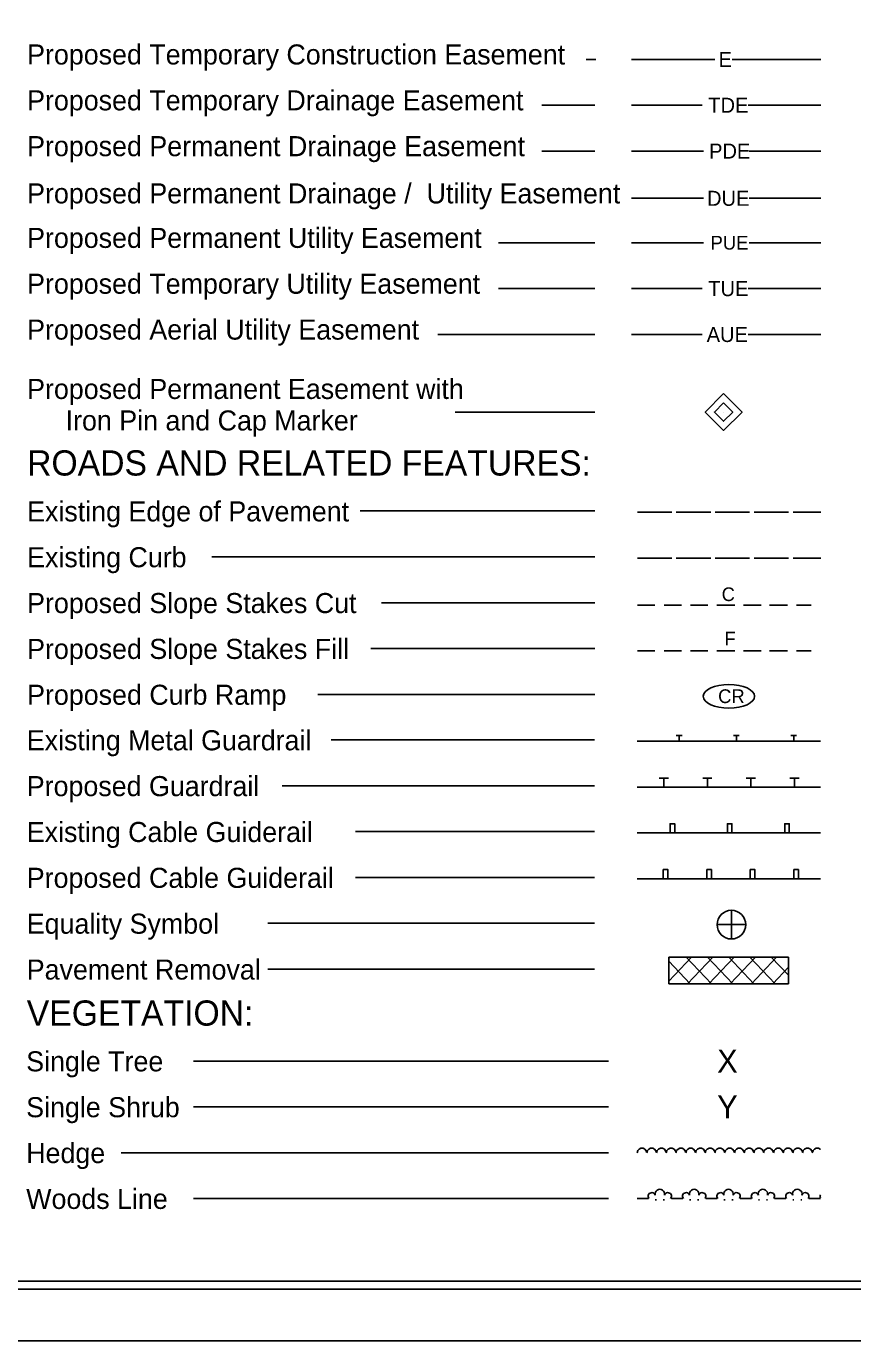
# Model space of a CAD drawing. Extents: x 573851.1 to 573884.7, y -53293.5 to -53271.5.
# Drawn here: x 573862.29 to 573869.5, y -53293.51 to -53282.04 of the extents above; entities that cross this region are included whole.
import ezdxf

# ---------------------------------------------------------------- set-up
doc = ezdxf.new("R2010")
doc.units = 0
for name, color, linetype in [('Prop Easement Permanent Drainage Utility', 7, 'Continuous'), ('Prop ROW Permanent Easement CELL', 7, 'Continuous'), ('Prop WCC CELL', 7, 'Continuous'), ('Sheet Cutting Line CELL', 7, 'Continuous'), ('Sheet Plot Border Inside CELL', 7, 'Continuous'), ('Sheet Plot Border Outside CELL', 7, 'Continuous'), ('Sheet Symbology CELL', 7, 'Continuous')]:
    doc.layers.add(name, color=color, linetype=linetype)

msp = doc.modelspace()

# ---------------------------------------------------------------- linework, layer by layer
at = {"layer": 'Prop Easement Permanent Drainage Utility'}
for p, q in [((573867.575, -53283.543), (573868.201, -53283.543)), ((573867.575, -53283.543), (573868.201, -53283.543)), ((573868.601, -53283.543), (573869.225, -53283.543)), ((573868.601, -53283.543), (573869.225, -53283.543))]:
    msp.add_line(p, q, dxfattribs=at)
at = {"layer": 'Prop ROW Permanent Easement CELL'}
msp.add_line((573868.378, -53285.408), (573868.378, -53285.408), dxfattribs=at)
for points in [[(573868.378, -53285.247), (573868.539, -53285.408), (573868.378, -53285.569), (573868.217, -53285.408)], [(573868.378, -53285.327), (573868.458, -53285.408), (573868.378, -53285.488), (573868.297, -53285.408)]]:
    msp.add_lwpolyline(points, close=True, dxfattribs=at)
at = {"layer": 'Prop WCC CELL'}
msp.add_ellipse((573868.424, -53287.888), major_axis=(0.224, 0), ratio=0.462467, dxfattribs=at)
at = {"layer": 'Sheet Cutting Line CELL'}
msp.add_line((573851.065, -53293.51), (573884.745, -53293.51), dxfattribs=at)
at = {"layer": 'Sheet Plot Border Inside CELL'}
msp.add_lwpolyline([(573851.325, -53293.061), (573884.655, -53293.061), (573884.655, -53271.959), (573851.325, -53271.959)], close=True, dxfattribs=at)
at = {"layer": 'Sheet Plot Border Outside CELL'}
msp.add_lwpolyline([(573851.065, -53293.51), (573884.745, -53293.51), (573884.745, -53271.51), (573851.065, -53271.51)], close=True, dxfattribs=at)
at = {"layer": 'Sheet Symbology CELL'}
for p, q in [((573867.262, -53282.331), (573867.179, -53282.331)), ((573867.575, -53282.331), (573867.627, -53282.331)), ((573867.627, -53282.331), (573868.302, -53282.331)), ((573868.452, -53282.331), (573869.127, -53282.331)), ((573869.127, -53282.331), (573869.225, -53282.331)), ((573867.254, -53282.731), (573866.791, -53282.731)), ((573867.575, -53282.731), (573867.642, -53282.731)), ((573867.642, -53282.731), (573868.192, -53282.731)), ((573868.592, -53282.731), (573869.142, -53282.731)), ((573869.142, -53282.731), (573869.225, -53282.731)), ((573867.254, -53283.131), (573866.791, -53283.131)), ((573867.575, -53283.131), (573867.651, -53283.131)), ((573867.651, -53283.131), (573868.201, -53283.131)), ((573868.601, -53283.131), (573869.151, -53283.131)), ((573869.151, -53283.131), (573869.225, -53283.131)), ((573867.254, -53283.931), (573866.412, -53283.931)), ((573867.575, -53283.931), (573867.652, -53283.931)), ((573867.652, -53283.931), (573868.202, -53283.931)), ((573868.602, -53283.931), (573869.152, -53283.931)), ((573869.152, -53283.931), (573869.225, -53283.931)), ((573867.254, -53284.331), (573866.412, -53284.331)), ((573867.575, -53284.331), (573867.642, -53284.331)), ((573867.642, -53284.331), (573868.192, -53284.331)), ((573868.592, -53284.331), (573869.142, -53284.331)), ((573869.142, -53284.331), (573869.225, -53284.331)), ((573867.254, -53284.731), (573865.885, -53284.731)), ((573867.575, -53284.731), (573867.642, -53284.731)), ((573867.642, -53284.731), (573868.192, -53284.731)), ((573868.592, -53284.731), (573869.142, -53284.731)), ((573869.142, -53284.731), (573869.225, -53284.731)), ((573867.254, -53285.408), (573866.034, -53285.408)), ((573867.254, -53286.271), (573865.207, -53286.271)), ((573867.625, -53286.282), (573867.925, -53286.282)), ((573867.965, -53286.282), (573868.265, -53286.282)), ((573868.305, -53286.282), (573868.605, -53286.282)), ((573868.645, -53286.282), (573868.945, -53286.282)), ((573868.985, -53286.282), (573869.225, -53286.282)), ((573867.254, -53286.671), (573863.911, -53286.671)), ((573867.625, -53286.682), (573867.925, -53286.682)), ((573867.965, -53286.682), (573868.265, -53286.682)), ((573868.305, -53286.682), (573868.605, -53286.682)), ((573868.645, -53286.682), (573868.945, -53286.682)), ((573868.985, -53286.682), (573869.225, -53286.682)), ((573867.254, -53287.071), (573865.391, -53287.071)), ((573867.625, -53287.092), (573867.777, -53287.092)), ((573868.011, -53287.092), (573867.86, -53287.092)), ((573868.241, -53287.092), (573868.089, -53287.092)), ((573868.476, -53287.092), (573868.32, -53287.092)), ((573868.705, -53287.092), (573868.55, -53287.092)), ((573868.936, -53287.092), (573868.779, -53287.092)), ((573869.142, -53287.092), (573869.014, -53287.092)), ((573867.254, -53287.471), (573865.3, -53287.471)), ((573867.625, -53287.492), (573867.777, -53287.492)), ((573868.011, -53287.492), (573867.86, -53287.492)), ((573868.241, -53287.492), (573868.089, -53287.492)), ((573868.476, -53287.492), (573868.32, -53287.492)), ((573868.705, -53287.492), (573868.55, -53287.492)), ((573868.936, -53287.492), (573868.779, -53287.492)), ((573869.142, -53287.492), (573869.014, -53287.492)), ((573867.254, -53287.871), (573864.836, -53287.871)), ((573867.965, -53288.23), (573868.015, -53288.23)), ((573867.99, -53288.28), (573867.99, -53288.23)), ((573868.465, -53288.23), (573868.515, -53288.23)), ((573868.49, -53288.28), (573868.49, -53288.23)), ((573868.965, -53288.23), (573869.015, -53288.23)), ((573868.99, -53288.28), (573868.99, -53288.23)), ((573867.251, -53288.268), (573864.954, -53288.268)), ((573867.622, -53288.28), (573869.222, -53288.28)), ((573867.251, -53288.668), (573864.526, -53288.668)), ((573869.222, -53288.68), (573867.622, -53288.68)), ((573867.816, -53288.601), (573867.896, -53288.601)), ((573867.856, -53288.68), (573867.856, -53288.601)), ((573868.196, -53288.601), (573868.276, -53288.601)), ((573868.236, -53288.68), (573868.236, -53288.601)), ((573868.576, -53288.601), (573868.656, -53288.601)), ((573868.616, -53288.68), (573868.616, -53288.601)), ((573868.956, -53288.601), (573869.036, -53288.601)), ((573868.996, -53288.68), (573868.996, -53288.601)), ((573867.251, -53289.068), (573865.165, -53289.068)), ((573867.622, -53289.08), (573869.222, -53289.08)), ((573867.251, -53289.468), (573865.165, -53289.468)), ((573867.622, -53289.48), (573869.222, -53289.48)), ((573868.446, -53289.755), (573868.446, -53289.88)), ((573867.251, -53289.868), (573864.399, -53289.868)), ((573868.321, -53289.88), (573868.446, -53289.88)), ((573868.446, -53289.88), (573868.446, -53290.005)), ((573868.446, -53289.88), (573868.571, -53289.88)), ((573867.901, -53290.163), (573868.943, -53290.163)), ((573867.901, -53290.397), (573867.901, -53290.163)), ((573867.901, -53290.175), (573867.912, -53290.163)), ((573867.901, -53290.374), (573868.098, -53290.163)), ((573868.272, -53290.397), (573868.052, -53290.163)), ((573868.064, -53290.397), (573868.284, -53290.163)), ((573868.457, -53290.397), (573868.238, -53290.163)), ((573868.249, -53290.397), (573868.47, -53290.163)), ((573868.643, -53290.397), (573868.423, -53290.163)), ((573868.435, -53290.397), (573868.655, -53290.163)), ((573868.829, -53290.397), (573868.608, -53290.163)), ((573868.621, -53290.397), (573868.84, -53290.163)), ((573868.943, -53290.322), (573868.794, -53290.163)), ((573868.943, -53290.163), (573868.943, -53290.397)), ((573867.251, -53290.268), (573864.399, -53290.268)), ((573868.086, -53290.397), (573867.901, -53290.199)), ((573868.806, -53290.397), (573868.943, -53290.251)), ((573868.943, -53290.397), (573867.901, -53290.397)), ((573867.374, -53291.07), (573863.751, -53291.07)), ((573867.374, -53291.47), (573863.751, -53291.47)), ((573867.374, -53291.87), (573863.12, -53291.87)), ((573867.622, -53291.87), (573867.628, -53291.851)), ((573867.628, -53291.851), (573867.64, -53291.838)), ((573867.64, -53291.838), (573867.656, -53291.829)), ((573867.656, -53291.829), (573867.675, -53291.829)), ((573867.675, -53291.829), (573867.691, -53291.839)), ((573867.691, -53291.839), (573867.702, -53291.852)), ((573867.702, -53291.852), (573867.706, -53291.869)), ((573867.707, -53291.87), (573867.713, -53291.851)), ((573867.713, -53291.851), (573867.725, -53291.838)), ((573867.725, -53291.838), (573867.741, -53291.829)), ((573867.741, -53291.829), (573867.76, -53291.829)), ((573867.76, -53291.829), (573867.776, -53291.839)), ((573867.776, -53291.839), (573867.787, -53291.852)), ((573867.787, -53291.852), (573867.791, -53291.869)), ((573867.792, -53291.87), (573867.798, -53291.851)), ((573867.798, -53291.851), (573867.81, -53291.838)), ((573867.81, -53291.838), (573867.826, -53291.829)), ((573867.826, -53291.829), (573867.845, -53291.829)), ((573867.845, -53291.829), (573867.861, -53291.839)), ((573867.861, -53291.839), (573867.872, -53291.852)), ((573867.872, -53291.852), (573867.876, -53291.869)), ((573867.877, -53291.87), (573867.883, -53291.851)), ((573867.883, -53291.851), (573867.895, -53291.838)), ((573867.895, -53291.838), (573867.911, -53291.829)), ((573867.911, -53291.829), (573867.93, -53291.829)), ((573867.93, -53291.829), (573867.946, -53291.839)), ((573867.946, -53291.839), (573867.957, -53291.852)), ((573867.957, -53291.852), (573867.961, -53291.869)), ((573867.962, -53291.87), (573867.968, -53291.851)), ((573867.968, -53291.851), (573867.98, -53291.838)), ((573867.98, -53291.838), (573867.996, -53291.829)), ((573867.996, -53291.829), (573868.015, -53291.829)), ((573868.015, -53291.829), (573868.031, -53291.839)), ((573868.031, -53291.839), (573868.042, -53291.852)), ((573868.042, -53291.852), (573868.046, -53291.869)), ((573868.047, -53291.87), (573868.053, -53291.851)), ((573868.053, -53291.851), (573868.065, -53291.838)), ((573868.065, -53291.838), (573868.081, -53291.829)), ((573868.081, -53291.829), (573868.1, -53291.829)), ((573868.1, -53291.829), (573868.116, -53291.839)), ((573868.116, -53291.839), (573868.127, -53291.852)), ((573868.127, -53291.852), (573868.131, -53291.869)), ((573868.132, -53291.87), (573868.138, -53291.851)), ((573868.138, -53291.851), (573868.15, -53291.838)), ((573868.15, -53291.838), (573868.166, -53291.829)), ((573868.166, -53291.829), (573868.185, -53291.829)), ((573868.185, -53291.829), (573868.201, -53291.839)), ((573868.201, -53291.839), (573868.212, -53291.852)), ((573868.212, -53291.852), (573868.216, -53291.869)), ((573868.217, -53291.87), (573868.223, -53291.851)), ((573868.223, -53291.851), (573868.235, -53291.838)), ((573868.235, -53291.838), (573868.251, -53291.829)), ((573868.251, -53291.829), (573868.27, -53291.829)), ((573868.27, -53291.829), (573868.286, -53291.839)), ((573868.286, -53291.839), (573868.297, -53291.852)), ((573868.297, -53291.852), (573868.301, -53291.869)), ((573868.302, -53291.87), (573868.308, -53291.851)), ((573868.308, -53291.851), (573868.32, -53291.838)), ((573868.32, -53291.838), (573868.336, -53291.829)), ((573868.336, -53291.829), (573868.355, -53291.829)), ((573868.355, -53291.829), (573868.371, -53291.839)), ((573868.371, -53291.839), (573868.382, -53291.852)), ((573868.382, -53291.852), (573868.386, -53291.869)), ((573868.387, -53291.87), (573868.393, -53291.851)), ((573868.393, -53291.851), (573868.405, -53291.838)), ((573868.405, -53291.838), (573868.421, -53291.829)), ((573868.421, -53291.829), (573868.44, -53291.829)), ((573868.44, -53291.829), (573868.456, -53291.839)), ((573868.456, -53291.839), (573868.467, -53291.852)), ((573868.467, -53291.852), (573868.471, -53291.869)), ((573868.472, -53291.87), (573868.478, -53291.851)), ((573868.478, -53291.851), (573868.49, -53291.838)), ((573868.49, -53291.838), (573868.506, -53291.829)), ((573868.506, -53291.829), (573868.525, -53291.829)), ((573868.525, -53291.829), (573868.541, -53291.839)), ((573868.541, -53291.839), (573868.552, -53291.852)), ((573868.552, -53291.852), (573868.556, -53291.869)), ((573868.557, -53291.87), (573868.563, -53291.851)), ((573868.563, -53291.851), (573868.575, -53291.838)), ((573868.575, -53291.838), (573868.591, -53291.829)), ((573868.591, -53291.829), (573868.61, -53291.829)), ((573868.61, -53291.829), (573868.626, -53291.839)), ((573868.626, -53291.839), (573868.637, -53291.852)), ((573868.637, -53291.852), (573868.641, -53291.869)), ((573868.642, -53291.87), (573868.648, -53291.851)), ((573868.648, -53291.851), (573868.66, -53291.838)), ((573868.66, -53291.838), (573868.676, -53291.829)), ((573868.676, -53291.829), (573868.695, -53291.829)), ((573868.695, -53291.829), (573868.711, -53291.839)), ((573868.711, -53291.839), (573868.722, -53291.852)), ((573868.722, -53291.852), (573868.726, -53291.869)), ((573868.727, -53291.87), (573868.733, -53291.851)), ((573868.733, -53291.851), (573868.745, -53291.838)), ((573868.745, -53291.838), (573868.761, -53291.829)), ((573868.761, -53291.829), (573868.78, -53291.829)), ((573868.78, -53291.829), (573868.796, -53291.839)), ((573868.796, -53291.839), (573868.807, -53291.852)), ((573868.807, -53291.852), (573868.811, -53291.869)), ((573868.812, -53291.87), (573868.818, -53291.851)), ((573868.818, -53291.851), (573868.83, -53291.838)), ((573868.83, -53291.838), (573868.846, -53291.829)), ((573868.846, -53291.829), (573868.865, -53291.829)), ((573868.865, -53291.829), (573868.881, -53291.839)), ((573868.881, -53291.839), (573868.892, -53291.852)), ((573868.892, -53291.852), (573868.896, -53291.869)), ((573868.897, -53291.87), (573868.903, -53291.851)), ((573868.903, -53291.851), (573868.915, -53291.838)), ((573868.915, -53291.838), (573868.931, -53291.829)), ((573868.931, -53291.829), (573868.95, -53291.829)), ((573868.95, -53291.829), (573868.966, -53291.839)), ((573868.966, -53291.839), (573868.977, -53291.852)), ((573868.977, -53291.852), (573868.981, -53291.869)), ((573868.982, -53291.87), (573868.988, -53291.851)), ((573868.988, -53291.851), (573869, -53291.838)), ((573869, -53291.838), (573869.016, -53291.829)), ((573869.016, -53291.829), (573869.035, -53291.829)), ((573869.035, -53291.829), (573869.051, -53291.839)), ((573869.051, -53291.839), (573869.062, -53291.852)), ((573869.062, -53291.852), (573869.066, -53291.869)), ((573869.067, -53291.87), (573869.073, -53291.851)), ((573869.073, -53291.851), (573869.085, -53291.838)), ((573869.085, -53291.838), (573869.101, -53291.829)), ((573869.101, -53291.829), (573869.12, -53291.829)), ((573869.12, -53291.829), (573869.136, -53291.839)), ((573869.136, -53291.839), (573869.147, -53291.852)), ((573869.147, -53291.852), (573869.151, -53291.869)), ((573869.152, -53291.87), (573869.158, -53291.851)), ((573869.158, -53291.851), (573869.17, -53291.838)), ((573869.17, -53291.838), (573869.186, -53291.829)), ((573869.186, -53291.829), (573869.205, -53291.829)), ((573869.205, -53291.829), (573869.221, -53291.839)), ((573869.221, -53291.839), (573869.222, -53291.84)), ((573867.374, -53292.27), (573863.751, -53292.27)), ((573867.622, -53292.27), (573867.722, -53292.27)), ((573867.781, -53292.28), (573867.791, -53292.28)), ((573867.851, -53292.28), (573867.861, -53292.28)), ((573867.922, -53292.27), (573868.022, -53292.27)), ((573868.081, -53292.28), (573868.091, -53292.28)), ((573868.151, -53292.28), (573868.161, -53292.28)), ((573868.222, -53292.27), (573868.322, -53292.27)), ((573868.381, -53292.28), (573868.391, -53292.28)), ((573868.451, -53292.28), (573868.461, -53292.28)), ((573868.522, -53292.27), (573868.622, -53292.27)), ((573868.681, -53292.28), (573868.691, -53292.28)), ((573868.751, -53292.28), (573868.761, -53292.28)), ((573868.822, -53292.27), (573868.922, -53292.27)), ((573868.981, -53292.28), (573868.991, -53292.28)), ((573869.051, -53292.28), (573869.061, -53292.28)), ((573869.122, -53292.27), (573869.222, -53292.27))]:
    msp.add_line(p, q, dxfattribs=at)
for points in [[(573884.405, -53272.01), (573854.405, -53272.01), (573854.405, -53292.989), (573884.405, -53292.989)], [(573867.911, -53289.08), (573867.951, -53289.08), (573867.951, -53289), (573867.911, -53289)], [(573868.411, -53289.08), (573868.451, -53289.08), (573868.451, -53289), (573868.411, -53289)], [(573868.911, -53289.08), (573868.951, -53289.08), (573868.951, -53289), (573868.911, -53289)], [(573867.851, -53289.4), (573867.891, -53289.4), (573867.891, -53289.48), (573867.851, -53289.48)], [(573868.231, -53289.4), (573868.271, -53289.4), (573868.271, -53289.48), (573868.231, -53289.48)], [(573868.611, -53289.4), (573868.651, -53289.4), (573868.651, -53289.48), (573868.611, -53289.48)], [(573868.991, -53289.4), (573869.031, -53289.4), (573869.031, -53289.48), (573868.991, -53289.48)]]:
    msp.add_lwpolyline(points, close=True, dxfattribs=at)
for centre, radius, start, end in [((573868.446, -53289.88), 0.125, 89.9944, 179.9989), ((573868.446, -53289.88), 0.125, 359.9944, 89.9989), ((573868.446, -53289.88), 0.125, 179.9944, 269.9989), ((573868.446, -53289.88), 0.125, 269.9944, 359.9989), ((573867.751, -53292.249), 0.0316, 18.435, 219.2315), ((573867.821, -53292.229), 0.0412, 345.9638, 194.0362), ((573867.891, -53292.249), 0.0316, 320.7685, 161.5651), ((573868.051, -53292.249), 0.0316, 18.435, 219.2315), ((573868.121, -53292.229), 0.0412, 345.9638, 194.0362), ((573868.191, -53292.249), 0.0316, 320.7685, 161.5651), ((573868.351, -53292.249), 0.0316, 18.435, 219.2315), ((573868.421, -53292.229), 0.0412, 345.9638, 194.0362), ((573868.491, -53292.249), 0.0316, 320.7685, 161.5651), ((573868.651, -53292.249), 0.0316, 18.435, 219.2315), ((573868.721, -53292.229), 0.0412, 345.9638, 194.0362), ((573868.791, -53292.249), 0.0316, 320.7685, 161.5651), ((573868.951, -53292.249), 0.0316, 18.435, 219.2315), ((573869.021, -53292.229), 0.0412, 345.9638, 194.0362), ((573869.091, -53292.249), 0.0316, 320.7685, 161.5651), ((573869.251, -53292.249), 0.0316, 156.251, 203.749)]:
    msp.add_arc(centre, radius, start, end, dxfattribs=at)

# ---------------------------------------------------------------- texts
at = {"layer": 'Prop Easement Permanent Drainage Utility'}
msp.add_text('DUE', height=0.131, dxfattribs=at).set_placement((573868.233, -53283.609))
msp.add_text('DUE', height=0.131, dxfattribs=at).set_placement((573868.233, -53283.609))
at = {"layer": 'Prop WCC CELL'}
msp.add_text('CR', height=0.12, dxfattribs=at).set_placement((573868.33, -53287.947))
at = {"layer": 'Sheet Symbology CELL'}
for s, height, p in [('Proposed Temporary Construction Easement', 0.175, (573862.299, -53282.376)), ('E', 0.131, (573868.334, -53282.397)), ('Proposed Temporary Drainage Easement', 0.175, (573862.299, -53282.776)), ('TDE', 0.131, (573868.244, -53282.797)), ('Proposed Permanent Drainage Easement', 0.175, (573862.299, -53283.176)), ('PDE', 0.131, (573868.251, -53283.197)), ('Proposed Permanent Drainage /  Utility Easement', 0.175, (573862.299, -53283.588)), ('Proposed Permanent Utility Easement', 0.175, (573862.299, -53283.976)), ('PUE', 0.12, (573868.264, -53283.991)), ('Proposed Temporary Utility Easement', 0.175, (573862.299, -53284.376)), ('TUE', 0.131, (573868.244, -53284.397)), ('Proposed Aerial Utility Easement', 0.175, (573862.299, -53284.776)), ('AUE', 0.131, (573868.23, -53284.797)), ('Proposed Permanent Easement with', 0.175, (573862.299, -53285.294)), ('Iron Pin and Cap Marker', 0.175, (573862.635, -53285.569)), ('ROADS AND RELATED FEATURES:', 0.22, (573862.299, -53285.962)), ('Existing Edge of Pavement', 0.175, (573862.299, -53286.362)), ('Existing Curb', 0.175, (573862.299, -53286.762)), ('Proposed Slope Stakes Cut', 0.175, (573862.299, -53287.162)), ('C', 0.119, (573868.361, -53287.057)), ('F', 0.119, (573868.385, -53287.444)), ('Proposed Slope Stakes Fill', 0.175, (573862.299, -53287.562)), ('Proposed Curb Ramp', 0.175, (573862.299, -53287.962)), ('Existing Metal Guardrail', 0.175, (573862.296, -53288.359)), ('Proposed Guardrail', 0.175, (573862.296, -53288.759)), ('Existing Cable Guiderail', 0.175, (573862.296, -53289.159)), ('Proposed Cable Guiderail', 0.175, (573862.296, -53289.559)), ('Equality Symbol', 0.175, (573862.296, -53289.959)), ('Pavement Removal', 0.175, (573862.296, -53290.359)), ('VEGETATION:', 0.22, (573862.296, -53290.761)), ('Single Tree', 0.175, (573862.291, -53291.16)), ('X', 0.2, (573868.322, -53291.17)), ('Single Shrub', 0.175, (573862.291, -53291.56)), ('Y', 0.2, (573868.322, -53291.57)), ('Hedge', 0.175, (573862.291, -53291.96)), ('Woods Line', 0.175, (573862.291, -53292.36))]:
    msp.add_text(s, height=height, dxfattribs=at).set_placement(p)

doc.saveas('drawing.dxf')
